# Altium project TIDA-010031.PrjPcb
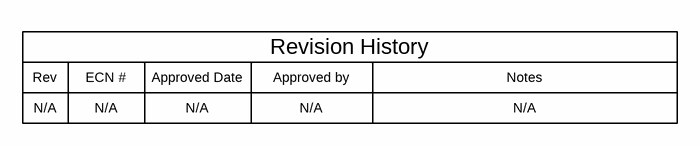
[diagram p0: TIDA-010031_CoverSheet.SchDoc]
CopyrightYear: 2018; PCB_Layout: Hawken; PCB_Rev: 1; PRJ_Customer: Public Release; PRJ_Engineer: Hawken Li; PRJ_Number: 010031; PRJ_Title: 100K RPM Motor Driver Module; SCH_Rev: 1; TechSupport: http://www.ti.com/support; TID: TIDA-010031
3 sheets, 87 parts. Net scope: global (net labels, ports and power ports of the same name join across sheets).
Board file: TIDA-010031.PcbDoc
Sheets:
  TIDA-010031_CoverSheet.SchDoc
  TIDA-010031_Page1.SchDoc
  TIDA-010031_EVM_Hardware.SchDoc

## Sheet TIDA-010031_CoverSheet.SchDoc
size 431 x 279 mm; Date: Not shown in title block; ApprovedBy: Not shown in title block; CheckedBy: Not shown in title block; Author: Not shown in title block; CompanyName: Not shown in title block; Engineer: Not shown in title block; Organization: Not shown in title block; Address1: Not shown in title block; Address2: Not shown in title block; Address3: Not shown in title block; Address4: Not shown in title block; DocumentNumber: 1; Revision: Use project parameter SCH_Rev; SheetNumber: 1; SheetTotal: 3; PageSetup: Record=PageOptions¦CenterHorizontal=True¦CenterVertical=True¦PrintScale=1.00¦XCorrection=1.00¦YCorrection=1.00¦PrintKind=0¦BorderSize=5000000¦LeftOffset=0¦BottomOffset=0¦Orientation=2¦PaperLength=1000¦PaperWidth=1000¦Scale=100¦PaperSource=15¦PrintQuality=600¦MediaType=1¦DitherType=10¦PaperKind=Letter¦PrintScaleMode=1

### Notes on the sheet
- Rev
- N/A
- ECN #
- Approved Date
- Approved by
- Revision History
- Notes

## Sheet TIDA-010031_Page1.SchDoc
size 431 x 279 mm; Date: Not shown in title block; ApprovedBy: Not shown in title block; CheckedBy: Not shown in title block; Author: Not shown in title block; CompanyName: Not shown in title block; Engineer: Not shown in title block; Organization: Not shown in title block; Address1: Not shown in title block; Address2: Not shown in title block; Address3: Not shown in title block; Address4: Not shown in title block; DocumentNumber: 1; Revision: Use project parameter SCH_Rev; SheetNumber: 2; SheetTotal: 3; PageSetup: Record=PageOptions¦CenterHorizontal=True¦CenterVertical=True¦PrintScale=1.00¦XCorrection=1.00¦YCorrection=1.00¦PrintKind=0¦BorderSize=5000000¦LeftOffset=0¦BottomOffset=0¦Orientation=2¦PaperLength=1000¦PaperWidth=1000¦Scale=100¦PaperSource=15¦PrintQuality=600¦MediaType=1¦DitherType=10¦PaperKind=Letter¦PrintScaleMode=1
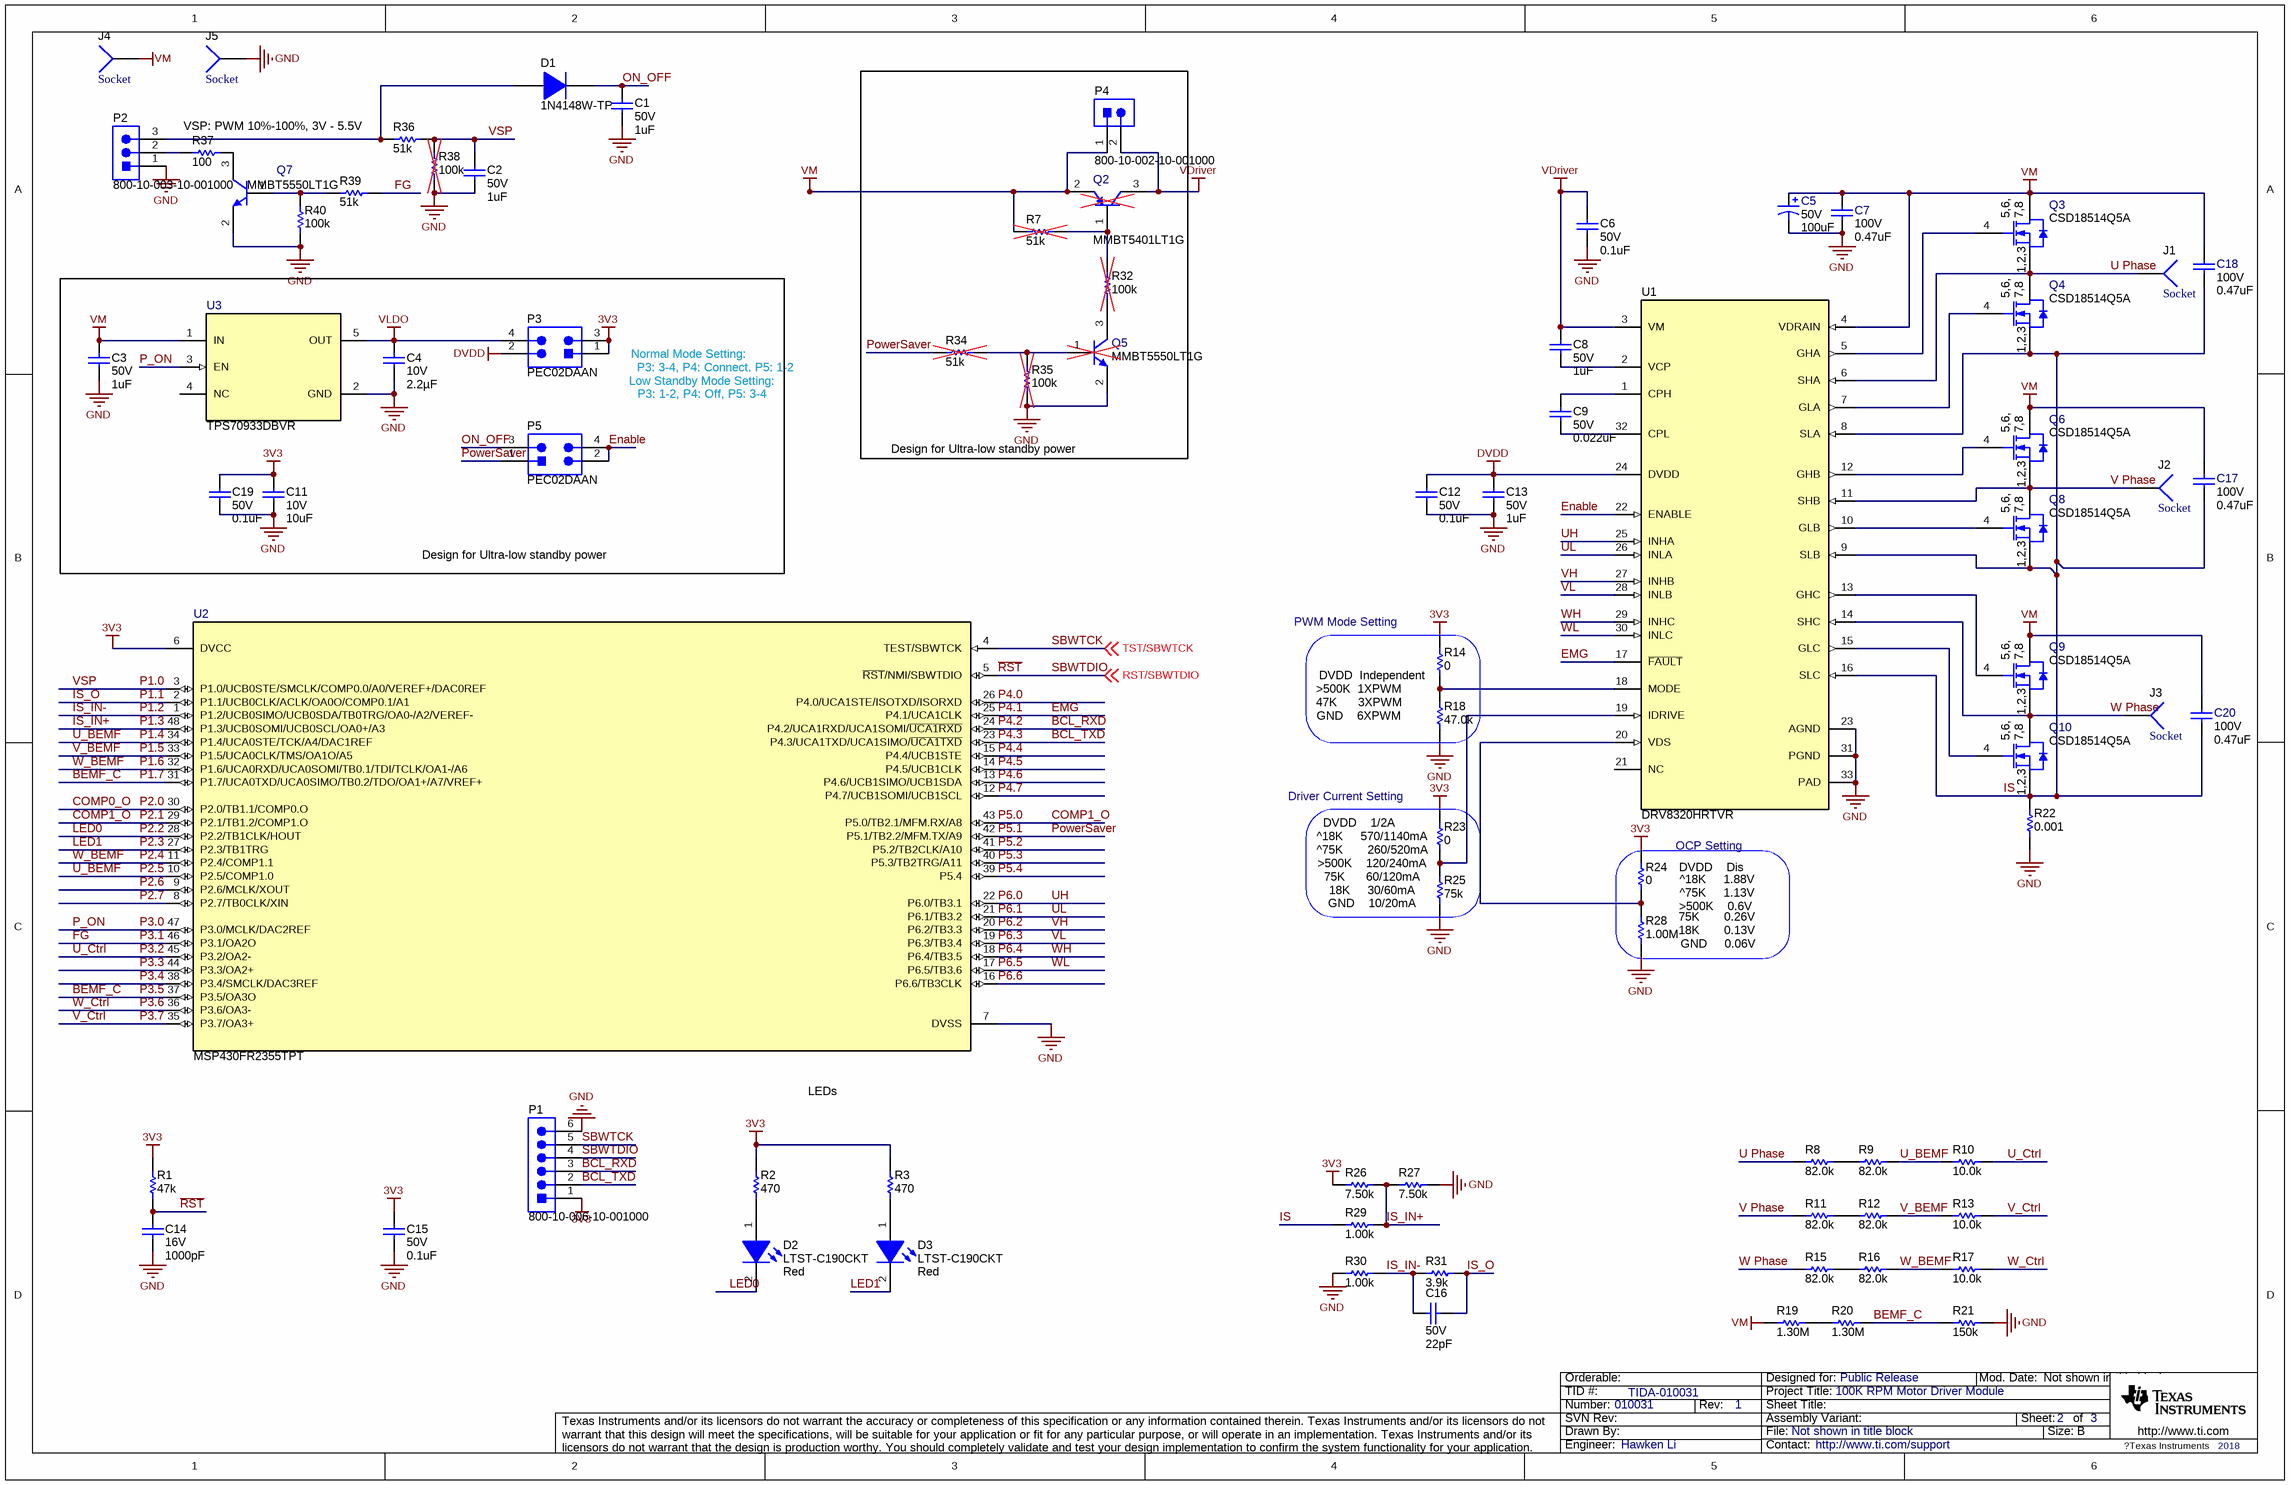
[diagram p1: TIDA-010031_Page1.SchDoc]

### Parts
C1  VDC_V: 50V  ValueDisplayed: 1uF  [0603]  (hidden comment: GRM188R61H105KAALD)
C2  VDC_V: 50V  ValueDisplayed: 1uF  [0603]  (hidden comment: C1608X5R1H104K080AA)
C3  VDC_V: 50V  ValueDisplayed: 1uF  [0603]  (hidden comment: GRM188R61H105KAALD)
C4  VDC_V: 10V  ValueDisplayed: 2.2µF  [0603]  (hidden comment: GRM188R71A225KE15J)
C5  VDC_V: 50V  ValueDisplayed: 100uF  [ZLJ_800X1150]  (hidden comment: 50ZLJ100MT78X11.5)
C6  VDC_V: 50V  ValueDisplayed: 0.1uF  [0603]  (hidden comment: C1608X5R1H104K080AA)
C7  VDC_V: 100V  ValueDisplayed: 0.47uF  [1206_180]  (hidden comment: C3216X7R2A474K160AA)
C8  VDC_V: 50V  ValueDisplayed: 1uF  [0603]  (hidden comment: GRM188R61H105KAALD)
C9  VDC_V: 50V  ValueDisplayed: 0.022uF  [0603]  (hidden comment: C0603X223K5RACTU)
C11  VDC_V: 10V  ValueDisplayed: 10uF  [0603]  (hidden comment: GRM188Z71A106MA73D)
C12  VDC_V: 50V  ValueDisplayed: 0.1uF  [0603]  (hidden comment: C1608X5R1H104K080AA)
C13  VDC_V: 50V  ValueDisplayed: 1uF  [0603]  (hidden comment: GRM188R61H105KAALD)
C14  VDC_V: 16V  ValueDisplayed: 1000pF  [0603]  (hidden comment: GRM188R71C102KA01D)
C15  VDC_V: 50V  ValueDisplayed: 0.1uF  [0603]  (hidden comment: C1608X5R1H104K080AA)
C16  VDC_V: 50V  ValueDisplayed: 22pF  [0603]  (hidden comment: 06035A220JAT2A)
C17  VDC_V: 100V  ValueDisplayed: 0.47uF  [1206_180]  (hidden comment: C3216X7R2A474K160AA)
C18  VDC_V: 100V  ValueDisplayed: 0.47uF  [1206_180]  (hidden comment: C3216X7R2A474K160AA)
C19  VDC_V: 50V  ValueDisplayed: 0.1uF  [0603]  (hidden comment: C1608X5R1H104K080AA)
C20  VDC_V: 100V  ValueDisplayed: 0.47uF  [1206_180]  (hidden comment: C3216X7R2A474K160AA)
D1  1N4148W-TP  [SOD-123]
D2  LTST-C190CKT  value Red  [LED_LTST-C190_Red]
D3  LTST-C190CKT  value Red  [LED_LTST-C190_Red]
J1  Socket  [PIN1]
J2  Socket  [PIN1]
J3  Socket  [PIN1]
J4  Socket  [PIN1]
J5  Socket  [PIN1]
P1  800-10-006-10-001000  [Mill-Max_800-10-006-10-001000]
P2  800-10-003-10-001000  [Mill-Max_800-10-003-10-001000]
P3  PEC02DAAN  [Sullins_PEC02DAAN]
P4  800-10-002-10-001000  [Mill-Max_800-10-002-10-001000]
P5  PEC02DAAN  [Sullins_PEC02DAAN]
Q2  MMBT5401LT1G  [SOT-23]
Q3  CSD18514Q5A  [DQJ0008A]
Q4  CSD18514Q5A  [DQJ0008A]
Q5  MMBT5550LT1G  [SOT-23]
Q6  CSD18514Q5A  [DQJ0008A]
Q7  MMBT5550LT1G  [SOT-23]
Q8  CSD18514Q5A  [DQJ0008A]
Q9  CSD18514Q5A  [DQJ0008A]
Q10  CSD18514Q5A  [DQJ0008A]
R1  ValueDisplayed: 47k  [0603]  (hidden comment: RC0603JR-0747KL)
R2  ValueDisplayed: 470  [0603]  (hidden comment: RC0603JR-07470RL)
R3  ValueDisplayed: 470  [0603]  (hidden comment: RC0603JR-07470RL)
R7  ValueDisplayed: 51k  [0603]  (hidden comment: RC0603JR-0751KL)
R8  ValueDisplayed: 82.0k  [0603]  (hidden comment: RC0603FR-0782KL)
R9  ValueDisplayed: 82.0k  [0603]  (hidden comment: RC0603FR-0782KL)
R10  ValueDisplayed: 10.0k  [0603]  (hidden comment: CRCW060315K0FKEA)
R11  ValueDisplayed: 82.0k  [0603]  (hidden comment: RC0603FR-0782KL)
R12  ValueDisplayed: 82.0k  [0603]  (hidden comment: RC0603FR-0782KL)
R13  ValueDisplayed: 10.0k  [0603]  (hidden comment: CRCW060315K0FKEA)
R14  ValueDisplayed: 0  [0603]  (hidden comment: RC0603JR-070RL)
R15  ValueDisplayed: 82.0k  [0603]  (hidden comment: RC0603FR-0782KL)
R16  ValueDisplayed: 82.0k  [0603]  (hidden comment: RC0603FR-0782KL)
R17  ValueDisplayed: 10.0k  [0603]  (hidden comment: CRCW060315K0FKEA)
R18  ValueDisplayed: 47.0k  [0603]  (hidden comment: CRCW060347K0FKEA)
R19  ValueDisplayed: 1.30M  [0603]  (hidden comment: CRCW06031M30FKEA)
R20  ValueDisplayed: 1.30M  [0603]  (hidden comment: CRCW06031M30FKEA)
R21  ValueDisplayed: 150k  [0603]  (hidden comment: CRCW0603150KFKEA)
R22  ValueDisplayed: 0.001  [2512]  (hidden comment: ERJ-M1WTF1M0U)
R23  ValueDisplayed: 0  [0603]  (hidden comment: RC0603JR-070RL)
R24  ValueDisplayed: 0  [0603]  (hidden comment: RC0603JR-070RL)
R25  ValueDisplayed: 75k  [0603]  (hidden comment: CRCW060375K0JNEA)
R26  ValueDisplayed: 7.50k  [0603]  (hidden comment: CRCW06037K50FKEA)
R27  ValueDisplayed: 7.50k  [0603]  (hidden comment: CRCW06037K50FKEA)
R28  ValueDisplayed: 1.00M  [0603]  (hidden comment: CRCW06031M00FKEA)
R29  ValueDisplayed: 1.00k  [0603]  (hidden comment: ERJ-3EKF1001V)
R30  ValueDisplayed: 1.00k  [0603]  (hidden comment: ERJ-3EKF1001V)
R31  ValueDisplayed: 3.9k  [0603]  (hidden comment: RC0603FR-0720KL)
R32  ValueDisplayed: 100k  [0603]  (hidden comment: ERJ-3GEYJ104V)
R34  ValueDisplayed: 51k  [0603]  (hidden comment: RC0603JR-0751KL)
R35  ValueDisplayed: 100k  [0603]  (hidden comment: ERJ-3GEYJ104V)
R36  ValueDisplayed: 51k  [0603]  (hidden comment: CRCW060351K0JNEA)
R37  ValueDisplayed: 100  [0603]  (hidden comment: CRCW0603100RJNEA)
R38  ValueDisplayed: 100k  [0603]  (hidden comment: ERJ-3GEYJ104V)
R39  ValueDisplayed: 51k  [0603]  (hidden comment: RC0603JR-0751KL)
R40  ValueDisplayed: 100k  [0603]  (hidden comment: ERJ-3GEYJ104V)
U1  DRV8320HRTVR  [RTV0032E]
U2  MSP430FR2355TPT  [PT0048A_N]
U3  TPS70933DBVR  [DBV0005A_N]

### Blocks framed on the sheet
Design for Ultra-low standby power: P4 Q2 Q5 R7 R32 R34 R35

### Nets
3V3: C11.1 C15.1 C19.1 P1.1 P3.1 P3.3 R1.2 R2.2 R3.2 R14.2 R23.2 R24.2 R26.1 U2.6(DVCC)
DVDD: C12.1 C13.1 P3.2 U1.24(DVDD)
GND: C1.2 C2.2 C3.2 C4.2 C5.2(-) C6.2 C7.2 C11.2 C12.2 C13.2 C14.2 C15.2 C19.2 J5.1 P1.6 P2.1 Q5.2(E) Q7.2(E) R18.1 R21.2 R22.1 R25.1 R27.2 R28.1 R30.1 R35.1 R38.1 R40.1 U1.23(AGND) U1.31(PGND) U1.33(PAD) U2.7(DVSS) U3.2(GND)
VDriver: C6.1 C8.1 P4.2 Q2.3(C) U1.3(VM)
VLDO: C4.1 P3.4 U3.5(OUT)
VM: C3.1 C5.1(+) C7.1 C17.1 C18.1 C20.1 J4.1 P4.1 Q2.2(E) Q3.5(D) Q3.6(D) Q3.7(D) Q3.8(D) Q3.9(D) Q6.5(D) Q6.6(D) Q6.7(D) Q6.8(D) Q6.9(D) Q9.5(D) Q9.6(D) Q9.7(D) Q9.8(D) Q9.9(D) R7.1 R19.1 U1.4(VDRAIN) U3.1(IN)
BCL_RXD: P1.3 U2.24(P4.2/UCA1RXD/UCA1SOMI/~{UCA1RXD})  [also labelled P4.2]
BCL_TXD: P1.2 U2.23(P4.3/UCA1TXD/UCA1SIMO/~{UCA1TXD})  [also labelled P4.3]
BEMF_C: R20.2 R21.1 U2.31(P1.7/UCA0TXD/UCA0SIMO/TB0.2/TDO/OA1+/A7/VREF+) U2.37(P3.5/OA3O)  [also labelled P1.7, P3.5]
COMP0_O: U2.30(P2.0/TB1.1/COMP0.O)  [also labelled P2.0]
COMP1_O: U2.29(P2.1/TB1.2/COMP1.O) U2.43(P5.0/TB2.1/MFM.RX/A8)  [also labelled P2.1, P5.0]
EMG: U1.17(~{FAULT}) U2.25(P4.1/UCA1CLK)  [also labelled P4.1]
Enable: P5.2 P5.4 U1.22(ENABLE)
FG: R39.2 U2.46(P3.1/OA2O)  [also labelled P3.1]
IS: C17.2 C18.2 C20.2 Q4.1(S) Q4.2(S) Q4.3(S) Q8.1(S) Q8.2(S) Q8.3(S) Q10.1(S) Q10.2(S) Q10.3(S) R22.2 R29.1 U1.8(SLA) U1.9(SLB) U1.16(SLC)
IS_IN+: R26.2 R27.1 R29.2 U2.48(P1.3/UCB0SOMI/UCB0SCL/OA0+/A3)  [also labelled P1.3]
IS_IN-: C16.2 R30.2 R31.1 U2.1(P1.2/UCB0SIMO/UCB0SDA/TB0TRG/OA0-/A2/VEREF-)  [also labelled P1.2]
IS_O: C16.1 R31.2 U2.2(P1.1/UCB0CLK/ACLK/OA0O/COMP0.1/A1)  [also labelled P1.1]
LED0: D2.2(K) U2.28(P2.2/TB1CLK/HOUT)  [also labelled P2.2]
LED1: D3.2(K) U2.27(P2.3/TB1TRG)  [also labelled P2.3]
ON_OFF: C1.1 D1.1(K) P5.3
P1.0: C2.1 R36.2 R38.2 U2.3(P1.0/UCB0STE/SMCLK/COMP0.0/A0/VEREF+/DAC0REF)  [also labelled VSP]
P1.4: R9.2 R10.1 U2.10(P2.5/COMP1.0) U2.34(P1.4/UCA0STE/TCK/A4/DAC1REF)  [also labelled P2.5, U_BEMF]
P1.5: R12.2 R13.1 U2.33(P1.5/UCA0CLK/TMS/OA1O/A5)  [also labelled V_BEMF]
P1.6: R16.2 R17.1 U2.11(P2.4/COMP1.1) U2.32(P1.6/UCA0RXD/UCA0SOMI/TB0.1/TDI/TCLK/OA1-/A6)  [also labelled P2.4, W_BEMF]
P2.6: U2.9(P2.6/MCLK/XOUT)
P2.7: U2.8(P2.7/TB0CLK/XIN)
P3.0: U2.47(P3.0/MCLK/DAC2REF) U3.3(EN)  [also labelled P_ON]
P3.2: R10.2 U2.45(P3.2/OA2-)  [also labelled U_Ctrl]
P3.3: U2.44(P3.3/OA2+)
P3.4: U2.38(P3.4/SMCLK/DAC3REF)
P3.6: R17.2 U2.36(P3.6/OA3-)  [also labelled W_Ctrl]
P3.7: R13.2 U2.35(P3.7/OA3+)  [also labelled V_Ctrl]
P4.0: U2.26(P4.0/UCA1STE/ISOTXD/ISORXD)
P4.4: U2.15(P4.4/UCB1STE)
P4.5: U2.14(P4.5/UCB1CLK)
P4.6: U2.13(P4.6/UCB1SIMO/UCB1SDA)
P4.7: U2.12(P4.7/UCB1SOMI/UCB1SCL)
P5.1: P5.1 R34.1 U2.42(P5.1/TB2.2/MFM.TX/A9)  [also labelled PowerSaver]
P5.2: U2.41(P5.2/TB2CLK/A10)
P5.3: U2.40(P5.3/TB2TRG/A11)
P5.4: U2.39(P5.4)
P6.0: U1.25(INHA) U2.22(P6.0/TB3.1)  [also labelled UH]
P6.1: U1.26(INLA) U2.21(P6.1/TB3.2)  [also labelled UL]
P6.2: U1.27(INHB) U2.20(P6.2/TB3.3)  [also labelled VH]
P6.3: U1.28(INLB) U2.19(P6.3/TB3.4)  [also labelled VL]
P6.4: U1.29(INHC) U2.18(P6.4/TB3.5)  [also labelled WH]
P6.5: U1.30(INLC) U2.17(P6.5/TB3.6)  [also labelled WL]
P6.6: U2.16(P6.6/TB3CLK)
~{RST}: C14.1 P1.4 R1.1 U2.5(~{RST}/NMI/SBWTDIO) ; off-sheet RST/SBWTDIO  [also labelled RST/SBWTDIO, SBWTDIO]
SBWTCK: P1.5 U2.4(TEST/SBWTCK) ; off-sheet TST/SBWTCK  [also labelled TST/SBWTCK]
U Phase: J1.1 Q3.1(S) Q3.2(S) Q3.3(S) Q4.5(D) Q4.6(D) Q4.7(D) Q4.8(D) Q4.9(D) R8.1 U1.6(SHA)
V Phase: J2.1 Q6.1(S) Q6.2(S) Q6.3(S) Q8.5(D) Q8.6(D) Q8.7(D) Q8.8(D) Q8.9(D) R11.1 U1.11(SHB)
W Phase: J3.1 Q9.1(S) Q9.2(S) Q9.3(S) Q10.5(D) Q10.6(D) Q10.7(D) Q10.8(D) Q10.9(D) R15.1 U1.14(SHC)
NetC8_2: C8.2 U1.2(VCP)
NetC9_1: C9.1 U1.1(CPH)
NetC9_2: C9.2 U1.32(CPL)
NetD1_2: D1.2(A) P2.3 R36.1
NetD2_1: D2.1(A) R2.1
NetD3_1: D3.1(A) R3.1
NetP2_2: P2.2 R37.1
NetQ2_1: Q2.1(B) R7.2 R32.2
NetQ3_4: Q3.4(G) U1.5(GHA)
NetQ4_4: Q4.4(G) U1.7(GLA)
NetQ5_1: Q5.1(B) R34.2 R35.2
NetQ5_3: Q5.3(C) R32.1
NetQ6_4: Q6.4(G) U1.12(GHB)
NetQ7_1: Q7.1(B) R39.1 R40.2
NetQ7_3: Q7.3(C) R37.2
NetQ8_4: Q8.4(G) U1.10(GLB)
NetQ9_4: Q9.4(G) U1.13(GHC)
NetQ10_4: Q10.4(G) U1.15(GLC)
NetR8_2: R8.2 R9.1
NetR11_2: R11.2 R12.1
NetR14_1: R14.1 R18.2 U1.18(MODE)
NetR15_2: R15.2 R16.1
NetR19_2: R19.2 R20.1
NetR23_1: R23.1 R25.2 U1.19(IDRIVE)
NetR24_1: R24.1 R28.2 U1.20(VDS)

Not connected (* = marked no-connect by the designer): U1 21(NC); U3 4(NC)

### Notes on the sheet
- (near R37) VSP: PWM 10%-100%, 3V - 5.5V
- (near P3) Normal Mode Setting:
- (near P3) P3: 3-4, P4: Connect. P5: 1-2
- Low Standby Mode Setting:
- P3: 1-2, P4: Off, P5: 3-4
- Design for Ultra-low standby power
- (near R14) PWM Mode Setting
- >500K  1XPWM
- 47K      3XPWM
- DVDD  Independent
- GND    6XPWM
- (near R23) Driver Current Setting
- DVDD    1/2A
- (near R23) ^18K     570/1140mA
- (near R23) ^75K       260/520mA
- >500K    120/240mA
- 75K      60/120mA
- (near R25) 18K     30/60mA
- (near R25) GND    10/20mA
- OCP Setting
- DVDD    Dis
- >500K    0.6V
- ^18K     1.88V
- ^75K     1.13V
- 75K       0.26V
- 18K       0.13V
- GND     0.06V
- LEDs

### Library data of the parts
C1 C3 C8 C13 = CMP-0007350-5: CAP, CERM, 1 uF, 50 V, +/- 10%, X5R, 0603; Manufacturer: MuRata; TaMin_C: -55°C; Polarized: N; SizeAreaWB_mm2: 4.68; Value1: Unknown; U/M: EA; Value: 1uF; TaMax_C: 85°C; SizeZ_mm: 1; SizeX_mm: 1.6; SizeY_mm: 0.8; SizeArea_mm2: 1.28; Cap_F: 1µF; AEC Category: Q200
C2 C6 C12 C15 C19 = CMP-0007010-5: CAP, CERM, 0.1 uF, 50 V, +/- 10%, X5R, 0603; Manufacturer: TDK; TaMin_C: -55°C; ESR_ohm: 0.0296; Polarized: N; SizeAreaWB_mm2: 4.68; Value1: 0.0296 ohm; U/M: EA; Value: 0.1uF; TaMax_C: 85°C; SizeZ_mm: 1; SizeX_mm: 1.6; SizeY_mm: 0.8; SizeArea_mm2: 1.28; Cap_F: 100nF; IRMS_A: 9.7199dA; AEC Category: Q200
C4 = CMP-0084284-1: CAP, CERM, 2.2 µF, 10 V,+/- 10%, X7R, AEC-Q200 Grade 1, 0603; Manufacturer: MuRata; SizeAreaWB_mm2: 4.68; Polarized: N; AEC Qualified: Y; SizeX_mm: 1.6; SizeZ_mm: 1; SizeY_mm: 0.8; U/M: EA; TaMin_C: -55°C; Value: 2.2uF; AEC Category: Q200; TaMax_C: 125°C; SizeArea_mm2: 1.28
C5 = CMP-0009787-2: CAP, AL, 100 uF, 50 V, +/- 20%, 0.12 ohm, TH; Manufacturer: Rubycon; TaMin_C: -40°C; ESR_ohm: 1.2d; Polarized: Y; SizeAreaWB_mm2: 100; U/M: EA; Value: 100uF; TaMax_C: 105°C; SizeZ_mm: 13; SizeX_mm: 8; Cap_Case: 8x11.5; SizeArea_mm2: 64; CompType: Capacitor; AEC Qualified: N; Cap_F: 100µF; IRMS_A: 9.5dA; AEC Category: Q200
C7 C17 C18 C20 = CMP-0008716-2: CAP, CERM, 0.47 uF, 100 V, +/- 10%, X7R, 1206; Manufacturer: TDK; TaMin_C: -55°C; ESR_ohm: 7.558m; Polarized: N; SizeAreaWB_mm2: 10.92; Value1: 0.007558 ohm; U/M: EA; Value: 0.47uF; TaMax_C: 125°C; SizeZ_mm: 1.8; SizeX_mm: 3.2; SizeY_mm: 1.6; SizeArea_mm2: 5.12; Cap_F: 470nF; IRMS_A: 2.64716A; AEC Category: Q200
C9 = CMP-0006984-4: CAP, CERM, 0.022 uF, 50 V, +/- 10%, X7R, 0603; Manufacturer: Kemet; TaMin_C: -55°C; Polarized: N; SizeAreaWB_mm2: 4.68; Value1: Unknown; U/M: EA; TaMax_C: 125°C; SizeZ_mm: 1; SizeX_mm: 1.6; SizeY_mm: 0.8; SizeArea_mm2: 1.28; Cap_F: 22nF; AEC Category: Q200
C11 = CMP-0007497-5: CAP, CERM, 10 uF, 10 V, +/- 20%, X7R, 0603; Manufacturer: MuRata; TaMin_C: -55°C; Polarized: N; SizeAreaWB_mm2: 4.68; Value1: Unknown; U/M: EA; Value: 10uF; TaMax_C: 125°C; SizeZ_mm: 1; SizeX_mm: 1.6; SizeY_mm: 0.8; SizeArea_mm2: 1.28; Cap_F: 10µF; AEC Category: Q200
C14 = CMP-0007376-4: CAP, CERM, 1000 pF, 16 V, +/- 10%, X7R, 0603; Manufacturer: MuRata; TaMin_C: -55°C; Polarized: N; SizeAreaWB_mm2: 4.68; Value1: Unknown; U/M: EA; Value: 1000pF; TaMax_C: 125°C; SizeZ_mm: 1; SizeX_mm: 1.6; SizeY_mm: 0.8; SizeArea_mm2: 1.28; Cap_F: 1nF; AEC Category: Q200
C16 = CMP-0006775-4: CAP, CERM, 22 pF, 50 V, +/- 5%, C0G/NP0, 0603; Manufacturer: AVX; TaMin_C: -55°C; ESR_ohm: 2.59d; Polarized: N; SizeAreaWB_mm2: 4.68; Value1: 0.259 ohm; U/M: EA; Value: 22pF; TaMax_C: 125°C; SizeZ_mm: 1; SizeX_mm: 1.6; SizeY_mm: 0.8; SizeArea_mm2: 1.28; AEC Category: Q200
D1 = CMP-0076974-1: Diode, Switching, 100 V, 0.15 A, SOD-123; Manufacturer: Micro Commercial Components; SizeAreaWB_mm2: 13.095; Vr_V: 100V; SizeArea_mm2: 6.545; TJmax_C: 150°C; AEC Category: Q101; Value: 100V; SizeZ_mm: 1.35; Green_REACh: Incomplete; Io_A: 1.5dA; Vf_V: 1.25V; SizeY_mm: 1.7; Green_Lifecycle: Not Set; U/M: EA; Value1: 0.15A; SizeX_mm: 3.85
D2 D3 = CMP-0002842-1: LED, Red, SMD; Manufacturer: Lite-On; Io_A: 20mA; Power_TotalModule: 62.5mW; Tjmax_C: 85°C; Value1: 0.0625W; U/M: EA; Vf_V: 2V
P1 = CMP-0055084-1: Header, 100mil, 6x1, TH; Manufacturer: Mill-Max; CT: FALSE; CNHeader: TRUE
P2 = CMP-0055086-1: Header, 100mil, 3x1, TH; Manufacturer: Mill-Max; CNHeader: TRUE; Green_Lifecycle: Active; Green_REACh: Passed; CT: FALSE
P3 P5 = CMP-0054558-1: Header, 100mil, 2x2, Tin, TH; Manufacturer: Sullins Connector Solutions; CNHeader: TRUE; Green_Lifecycle: Not Set; Green_REACh: Incomplete; CT: FALSE
P4 = CMP-0055085-1: Header, 100mil, 2x1, TH; Manufacturer: Mill-Max; CNHeader: TRUE; Green_Lifecycle: Active; Green_REACh: Passed; CT: FALSE
Q2 = CMP-0000333-2: Transistor, PNP, 150 V, 0.5 A, SOT-23; Manufacturer: ON Semiconductor; TaMax_C: 150°C; Value2: 240; Value1: 0.5 A; Vcesat1_V: 5dV; SizeX_mm: 2.5; SizeY_mm: 3; TaMin_C: -55°C; IcRated_A: 5dA; CompType: BJT; SizeZ_mm: 1.1; Value: 150 V; SizeArea_mm2: 7.5; NPN: 0; Vceo_V: 150V; PNP: 1; AEC Category: Q101; SizeAreaWB_mm2: 14; U/M: EA
Q3 Q4 Q6 Q8-Q10 = CMP-0000715-1: MOSFET, N-CH, 40 V, 50 A, DQJ0008A (VSONP-8); Alternate Manufacturer: None; Manufacturer: Texas Instruments; SizeZ_mm: 1.1; ChType: N; Value2: 29 nC; Value1: 0.007; VdsMax_V: 40V; SizeX_mm: 6; SizeY_mm: 4.9; Vgs_V: 20V; Value: 40V; Rdson45_ohm: 7.9m; SizeArea_mm2: 29.4; AEC Category: Q101; IdsMax_A: 50A; SizeAreaWB_mm2: 55.2; U/M: EA; QgTyp_nC: 29
Q5 Q7 = CMP-0000411-2: Transistor, NPN, 140 V, 0.6 A, SOT-23; Manufacturer: ON Semiconductor; TaMax_C: 150°C; Value2: 250; Value1: 0.6 A; Vcesat1_V: 2.5dV; SizeX_mm: 2.5; SizeY_mm: 3; TaMin_C: -55°C; IcRated_A: 6dA; CompType: BJT; SizeZ_mm: 1.1; Value: 140 V; SizeArea_mm2: 7.5; NPN: 1; Vceo_V: 140V; PNP: 0; AEC Category: Q101; SizeAreaWB_mm2: 14; U/M: EA
R1 = CMP-0025925-5: RES, 47 k, 5%, 0.1 W, 0603; Manufacturer: Yageo; Power_W: 100mW; TempCo: 100 ppm/C; Value_Code: 47k0; Value: 47k; EIA_Code: E24; SizeX_mm: 1.6; SizeY_mm: 0.8; SizeZ_mm: 1; Value2: 0.1W; SizeArea_mm2: 1.28; AEC Qualified: N; VDC_V: 75V; AEC Category: Q200; SizeAreaWB_mm2: 4.68
R2 R3 = CMP-0025924-5: RES, 470, 5%, 0.1 W, 0603; Manufacturer: Yageo; Power_W: 100mW; TempCo: 100 ppm/C; Value_Code: 470R; Value: 470; EIA_Code: E24; SizeX_mm: 1.6; SizeY_mm: 0.8; SizeZ_mm: 1; Value2: 0.1W; SizeArea_mm2: 1.28; AEC Qualified: N; VDC_V: 75V; AEC Category: Q200; SizeAreaWB_mm2: 4.68
R7 R34 R39 = CMP-0025929-5: RES, 51 k, 5%, 0.1 W, 0603; Manufacturer: Yageo; Power_W: 100mW; TempCo: 100 ppm/C; Value_Code: 51k0; Value: 51k; EIA_Code: E24; SizeX_mm: 1.6; SizeY_mm: 0.8; SizeZ_mm: 1; Value2: 0.1W; SizeArea_mm2: 1.28; AEC Qualified: N; VDC_V: 75V; AEC Category: Q200; SizeAreaWB_mm2: 4.68
R8 R9 R11 R12 R15 R16 = CMP-0023292-5: RES, 82.0 k, 1%, 0.1 W, 0603; Manufacturer: Yageo; Power_W: 100mW; TempCo: 100 ppm/C; Value_Code: 82k0; Value: 82.0k; Res_ohm: 82k; SizeX_mm: 1.6; SizeY_mm: 0.8; SizeZ_mm: 1; Value2: 0.1W; SizeArea_mm2: 1.28; AEC Qualified: N; VDC_V: 75V; AEC Category: Q200; SizeAreaWB_mm2: 4.68
R10 R13 R17 = CMP-0022066-4: RES, 15.0 k, 1%, 0.1 W, AEC-Q200 Grade 0, 0603; Manufacturer: Vishay-Dale; Power_W: 100mW; TempCo: 100 ppm/C; Value_Code: 15k0; Value: 15.0k; EIA_Code: E96; Res_ohm: 15k; SizeX_mm: 1.6; SizeY_mm: 0.8; SizeZ_mm: 1; Value2: 0.1W; SizeArea_mm2: 1.28; AEC Qualified: Y; VDC_V: 75V; AEC Category: Q200; AEC Grade: 0
R14 R23 R24 = CMP-0025885-5: RES, 0, 5%, 0.1 W, 0603; Manufacturer: Yageo; Power_W: 100mW; TempCo: 200 ppm/C; Value_Code: 0000; Value: 0; EIA_Code: E24; SizeX_mm: 1.6; SizeZ_mm: 1; Value2: 0.1W; SizeArea_mm2: 1.28; AEC Qualified: N; VDC_V: 75V; AEC Category: Q200; SizeY_mm: 0.8; SizeAreaWB_mm2: 4.68
R18 = CMP-0022438-4: RES, 47.0 k, 1%, 0.1 W, AEC-Q200 Grade 0, 0603; Manufacturer: Vishay-Dale; Power_W: 100mW; TempCo: 100 ppm/C; Value_Code: 47k0; Value: 47.0k; Res_ohm: 47k; SizeX_mm: 1.6; SizeY_mm: 0.8; SizeZ_mm: 1; Value2: 0.1W; SizeArea_mm2: 1.28; AEC Qualified: Y; VDC_V: 75V; AEC Grade: 0; AEC Category: Q200
R19 R20 = CMP-0022150-4: RES, 1.30 M, 1%, 0.1 W, AEC-Q200 Grade 0, 0603; Manufacturer: Vishay-Dale; Power_W: 100mW; TempCo: 100 ppm/C; Value_Code: 1M30; Value: 1.30Meg; EIA_Code: E96; Res_ohm: 1.3M; SizeX_mm: 1.6; SizeY_mm: 0.8; SizeZ_mm: 1; Value2: 0.1W; SizeArea_mm2: 1.28; AEC Qualified: Y; VDC_V: 75V; AEC Category: Q200; AEC Grade: 0
R21 = CMP-0022060-4: RES, 150 k, 1%, 0.1 W, AEC-Q200 Grade 0, 0603; Manufacturer: Vishay-Dale; Power_W: 100mW; TempCo: 100 ppm/C; Value: 150k; EIA_Code: E96; SizeX_mm: 1.6; SizeY_mm: 0.8; SizeZ_mm: 1; Value2: 0.1W; SizeArea_mm2: 1.28; AEC Qualified: Y; VDC_V: 75V; AEC Category: Q200; AEC Grade: 0
R22 = CMP-0015817-2: RES, 0.001, 1%, 1 W, 2512; Manufacturer: Panasonic; Power_W: 1W; TempCo: ppm/C; Value_Code: 1L000; U/M: EA; Value: 0.001; EIA_Code: E96; Res_ohm: 1m; SizeX_mm: 6.3; SizeY_mm: 3.2; SizeZ_mm: 0.71; SizeArea_mm2: 20.16; AEC Category: Q200
R25 = CMP-0025853-4: RES, 75 k, 5%, 0.1 W, AEC-Q200 Grade 0, 0603; Manufacturer: Vishay-Dale; Power_W: 100mW; TempCo: 200 ppm/C; Value_Code: 75k0; Value: 75k; EIA_Code: E24; SizeX_mm: 1.6; SizeY_mm: 0.8; SizeZ_mm: 1; Value2: 0.1W; SizeArea_mm2: 1.28; AEC Qualified: Y; VDC_V: 75V; AEC Category: Q200; AEC Grade: 0
R26 R27 = CMP-0022601-4: RES, 7.50 k, 1%, 0.1 W, AEC-Q200 Grade 0, 0603; Manufacturer: Vishay-Dale; Power_W: 100mW; TempCo: 100 ppm/C; Value_Code: 7k50; Value: 7.50k; EIA_Code: E96; Res_ohm: 7.5k; SizeX_mm: 1.6; SizeY_mm: 0.8; SizeZ_mm: 1; Value2: 0.1W; SizeArea_mm2: 1.28; AEC Qualified: Y; VDC_V: 75V; AEC Category: Q200; AEC Grade: 0
R28 = CMP-0022138-4: RES, 1.00 M, 1%, 0.1 W, AEC-Q200 Grade 0, 0603; Manufacturer: Vishay-Dale; Power_W: 100mW; TempCo: 100 ppm/C; Value_Code: 1M00; Value: 1.00Meg; EIA_Code: E96; Res_ohm: 1M; SizeX_mm: 1.6; SizeY_mm: 0.8; SizeZ_mm: 1; Value2: 0.1W; SizeArea_mm2: 1.28; AEC Qualified: Y; VDC_V: 75V; AEC Category: Q200; AEC Grade: 0
R29 R30 = CMP-0022680-4: RES, 1.00 k, 1%, 0.1 W, 0603; Manufacturer: Panasonic; Power_W: 100mW; TempCo: 100 ppm/C; Value_Code: 1k00; U/M: EA; Value: 1.00k; EIA_Code: E96; Res_ohm: 1k; SizeX_mm: 1.6; SizeY_mm: 0.8; SizeZ_mm: 1; SizeArea_mm2: 1.28; VDC_V: 75V; AEC Category: Q200; Value2: 0.1W
R31 = CMP-0022906-5: RES, 20.0 k, 1%, 0.1 W, 0603; Manufacturer: Yageo; Power_W: 100mW; TempCo: 100 ppm/C; Value_Code: 20k0; Value: 20.0k; EIA_Code: E96; Res_ohm: 20k; SizeX_mm: 1.6; SizeY_mm: 0.8; SizeZ_mm: 1; Value2: 0.1W; SizeArea_mm2: 1.28; AEC Qualified: N; VDC_V: 75V; AEC Category: Q200; SizeAreaWB_mm2: 4.68
R32 R35 R38 R40 = CMP-0025875-3: RES, 100 k, 5%, 0.1 W, AEC-Q200 Grade 0, 0603; Manufacturer: Panasonic; Power_W: 100mW; TempCo: 200 ppm/C; U/M: EA; Value: 100k; EIA_Code: E24; SizeX_mm: 1.6; SizeY_mm: 0.8; SizeZ_mm: 1; Value2: 0.1W; SizeArea_mm2: 1.28; AEC Qualified: Y; VDC_V: 50V; AEC Grade: 0; AEC Category: Q200
R36 = CMP-0025824-4: RES, 51 k, 5%, 0.1 W, AEC-Q200 Grade 0, 0603; Manufacturer: Vishay-Dale; Power_W: 100mW; TempCo: 200 ppm/C; Value_Code: 51k0; Value: 51k; EIA_Code: E24; SizeX_mm: 1.6; SizeY_mm: 0.8; SizeZ_mm: 1; Value2: 0.1W; SizeArea_mm2: 1.28; AEC Qualified: Y; VDC_V: 75V; AEC Category: Q200; AEC Grade: 0
R37 = CMP-0025700-4: RES, 100, 5%, 0.1 W, AEC-Q200 Grade 0, 0603; Manufacturer: Vishay-Dale; Power_W: 100mW; TempCo: 200 ppm/C; Value_Code: 100R; Value: 100; EIA_Code: E24; SizeX_mm: 1.6; SizeY_mm: 0.8; SizeZ_mm: 1; Value2: 0.1W; SizeArea_mm2: 1.28; AEC Qualified: Y; VDC_V: 75V; AEC Category: Q200; AEC Grade: 0
U1 = CMP-0078607-1: 60V Three-Phase Smart Gate Driver, RTV0032E (WQFN-32); Alternate PartNumber: DRV8320HRTVT; Alternate Manufacturer: Texas Instruments; SizeAreaWB_mm2: 49; SizeZ_mm: 0.8; SizeX_mm: 5; SizeArea_mm2: 25; CompType: IC; AEC Qualified: N; AEC Category: Q200
U2 = CMP-0013603-2: Mixed-Signal Microcontroller, PT0048A (LQFP-48); Manufacturer: Texas Instruments; SizeX_mm: 9; CompType: IC; SizeZ_mm: 1.6; SizeArea_mm2: 81; SizeAreaWB_mm2: 121; U/M: EA
U3 = CMP-0073793-1: 150-mA, 30-V, Ultra-Low IQ, Wide Input Low-Dropout Regulator with Reverse Current Protection, DBV0005A (SOT-23-5); Alternate PartNumber: TPS70933DBVT; Alternate Manufacturer: Texas Instruments; Green_Lifecycle: Active; SizeAreaWB_mm2: 14.82; Green_REACh: Passed; U/M: EA; SizeZ_mm: 1.45; SizeX_mm: 2.8; SizeY_mm: 2.9; SizeArea_mm2: 8.12; CompType: IC

## Sheet TIDA-010031_EVM_Hardware.SchDoc: 100K RPM Motor Driver Module
size 431 x 279 mm; VersionControl_RevNumber: 1.0; Date: Not shown in title block; ApprovedBy: Not shown in title block; CheckedBy: Not shown in title block; Author: Not shown in title block; CompanyName: Not shown in title block; DrawnBy: Hawken Li; Engineer: Not shown in title block; Organization: Not shown in title block; Address1: Not shown in title block; Address2: Not shown in title block; Address3: Not shown in title block; Address4: Not shown in title block; DocumentNumber: 1; Revision: Use project parameter SCH_Rev; SheetNumber: 3; SheetTotal: 3; PageSetup: Record=PageOptions¦CenterHorizontal=True¦CenterVertical=True¦PrintScale=1.00¦XCorrection=1.00¦YCorrection=1.00¦PrintKind=0¦BorderSize=5000000¦LeftOffset=0¦BottomOffset=0¦Orientation=2¦PaperLength=1000¦PaperWidth=1000¦Scale=100¦PaperSource=15¦PrintQuality=600¦MediaType=1¦DitherType=10¦PaperKind=Letter¦PrintScaleMode=1
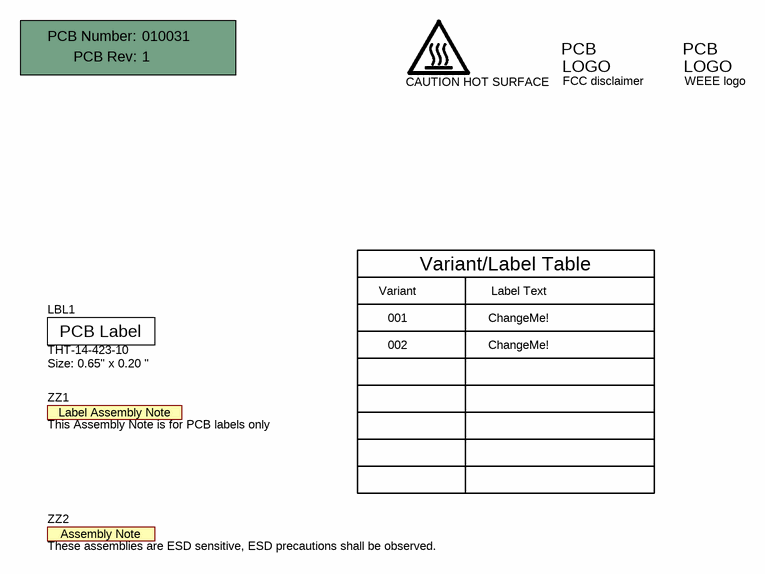
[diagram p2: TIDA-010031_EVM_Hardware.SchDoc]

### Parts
!PCB  Printed Circuit Board  (value not drawn)  (mechanical)
LBL1  THT-14-423-10  Note: Size: 0.65" x 0.20 "  [Label_650x200]
Logo3  FCC disclaimer  [FCC_disclaimer]  (no BOM)
Logo4  WEEE logo  [WEEE_Minimum]  (no BOM)
LOGO?  CAUTION HOT SURFACE  [IEC_HotSurface_Large]  (no BOM)
ZZ1  This Assembly Note is for PCB labels only  [AssemblyNoteLabel]  (no BOM)
ZZ2  These assemblies are ESD sensitive, ESD precautions shall be observed.  [AssemblyNote]  (no BOM)

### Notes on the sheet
- Variant
- Variant/Label Table
- Label Text
- 001
- 002
- ChangeMe!

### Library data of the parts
!PCB = CMP-0003618-2: Manufacturer: Any; PartNumber: 010031
LBL1 = CMP-0003625-1: Thermal Transfer Printable Labels, 0.650" W x 0.200" H - 10,000 per roll; Manufacturer: Brady; CompType: Label
Logo3 = CMP-0074847-1: FCC_disclaimer; Library Reference: Logo
Logo4 = CMP-0074769-1
LOGO? = CMP-0074837-1: IEC 61010-1 Hot Surface Warning; Library Reference: IEC_HotSurface; SymbolCreator: a0412235
ZZ1 = CMP-0003616-3
ZZ2 = CMP-0077236-1

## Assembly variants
001: not fitted FID1 FID2 FID3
